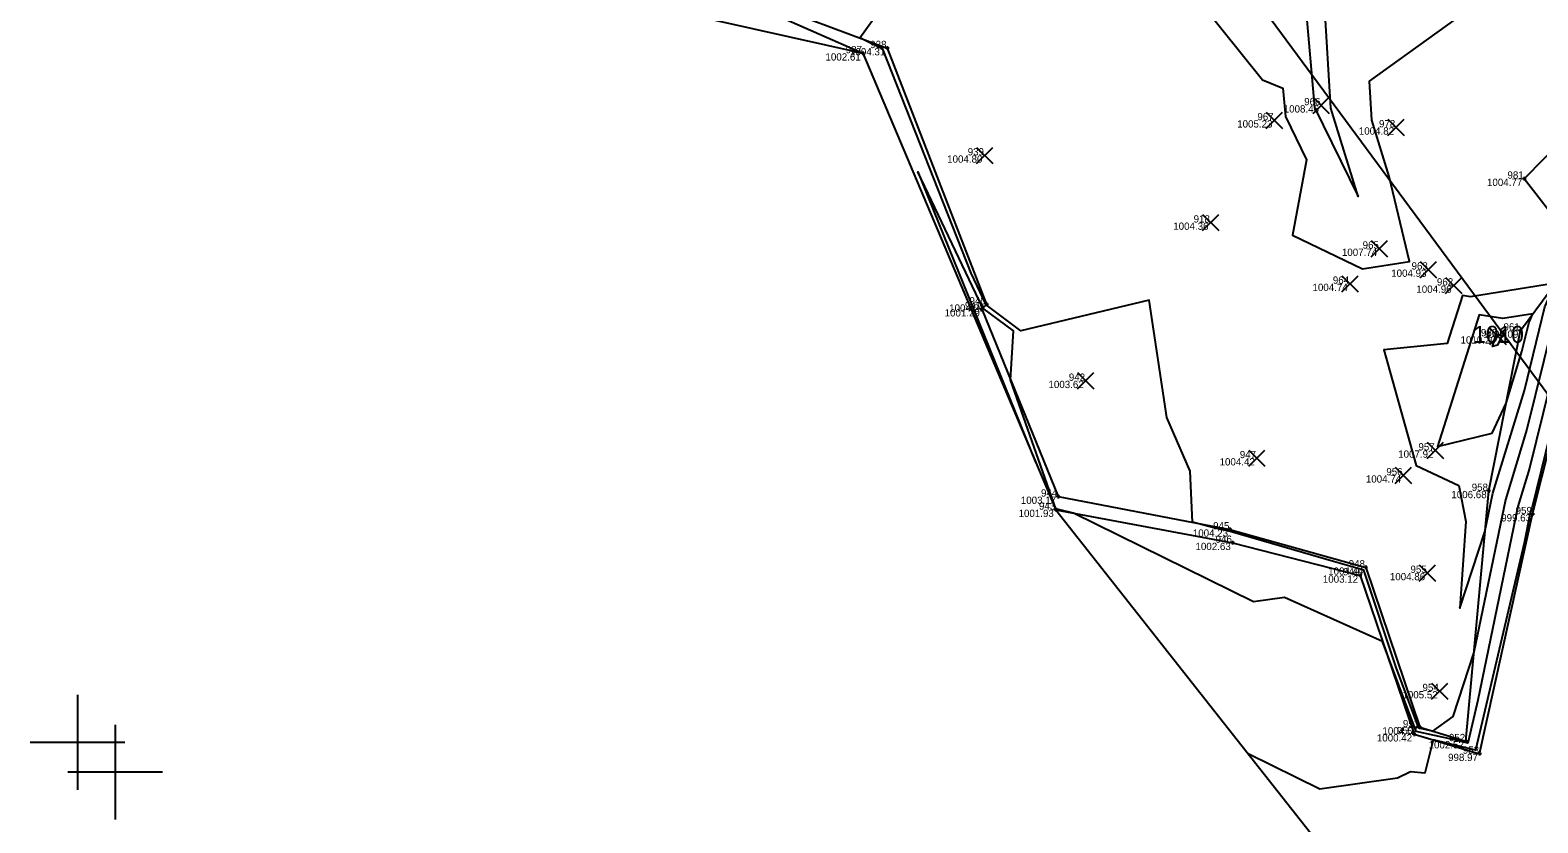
# Model space of a CAD drawing. Extents: x 2354693 to 2355622, y 637071 to 710080.
# Drawn here: x 2355009.4 to 2355257.5, y 709192.3 to 709322.8 of the extents above; entities that cross this region are included whole.
import ezdxf

# ---------------------------------------------------------------- set-up
doc = ezdxf.new("R2010")
doc.units = 0
for name, color, linetype in [('Default', 7, 'Continuous'), ('DT_X_Contour_Major', 7, 'Continuous'), ('DT_X_Contour_Minor', 7, 'Continuous'), ('HY_X_Water_Edge', 7, 'Continuous'), ('SV_X_Random_Point', 7, 'Continuous'), ('SV_X_Shot_Marker', 7, 'Continuous'), ('SV_X_Text_Elevation', 7, 'Continuous'), ('SV_X_Text_Name', 7, 'Continuous'), ('SV_X_Toe_of_Slope', 7, 'Continuous'), ('SV_X_Top_of_Bank', 7, 'Continuous'), ('VG_X_Tree_Line_Rt', 7, 'Continuous')]:
    doc.layers.add(name, color=color, linetype=linetype)

msp = doc.modelspace()

# ---------------------------------------------------------------- linework, layer by layer
at = {"layer": 'Default'}
for p, q in [((2355017.22, 709213.35), (2355017.22, 709197.75)), ((2355023.41, 709208.46), (2355023.41, 709192.86)), ((2355025.02, 709205.55), (2355009.42, 709205.55)), ((2355031.21, 709200.66), (2355015.61, 709200.66))]:
    msp.add_line(p, q, dxfattribs=at)
msp.add_lwpolyline([(2355192.85, 709575.71), (2355160.05, 709542.81), (2355116.76, 709509.42), (2355081.06, 709480.43), (2355058.46, 709461.11), (2355065.45, 709426.86), (2355078.86, 709361.48), (2355116.19, 709325.77), (2355146.4, 709319.01), (2355178.16, 709243.86), (2355227.43, 709181.3), (2355213.36, 709127.54), (2355205.69, 709069.16), (2355203.89, 709062.28), (2355168.12, 708973.83)], dxfattribs=at)
msp.add_lwpolyline([(2355192.85, 709575.71), (2355160.05, 709542.81), (2355116.76, 709509.42), (2355081.06, 709480.43), (2355058.46, 709461.11), (2355065.45, 709426.86), (2355078.86, 709361.48), (2355116.19, 709325.77), (2355146.4, 709319.01), (2355178.16, 709243.86), (2355227.43, 709181.3), (2355213.36, 709127.54), (2355205.69, 709069.16), (2355203.89, 709062.28), (2355168.12, 708973.83)], dxfattribs=at)
at = {"layer": 'DT_X_Contour_Major'}
for points in [[(2355250.64, 709272.73), (2355251.6, 709272.58), (2355250.84, 709270.94), (2355250.01, 709270.74), (2355250.64, 709272.73)], [(2355250.64, 709272.73), (2355251.6, 709272.58), (2355250.84, 709270.94), (2355250.01, 709270.74), (2355250.64, 709272.73)], [(2355259.45, 709256.12), (2355256.53, 709244.3), (2355256.24, 709243.32), (2355255.21, 709238.35), (2355247.24, 709204.27), (2355240.26, 709205.95), (2355238.9, 709200.49), (2355236.53, 709200.69), (2355234.37, 709199.64), (2355221.59, 709197.85), (2355209.81, 709203.68)], [(2355259.45, 709256.12), (2355256.53, 709244.3), (2355256.24, 709243.32), (2355255.21, 709238.35), (2355247.24, 709204.27), (2355240.26, 709205.95), (2355238.9, 709200.49), (2355236.53, 709200.69), (2355234.37, 709199.64), (2355221.59, 709197.85), (2355209.81, 709203.68)]]:
    msp.add_lwpolyline(points, dxfattribs=at)
at = {"layer": 'DT_X_Contour_Minor'}
for points in [[(2355223.4, 709309.98), (2355222.4, 709327.22), (2355227.34, 709330.79), (2355220.07, 709333.56), (2355207.66, 709335.32), (2355213.86, 709359.23), (2355219.29, 709363.85), (2355215.74, 709367.58), (2355211.47, 709363.79), (2355205.57, 709361.18), (2355209.61, 709356.62), (2355205.47, 709333.93), (2355207.14, 709331.84), (2355219.24, 709326.97), (2355220.73, 709310.09), (2355227.94, 709295.41), (2355223.4, 709309.98)], [(2355223.4, 709309.98), (2355222.4, 709327.22), (2355227.34, 709330.79), (2355220.07, 709333.56), (2355207.66, 709335.32), (2355213.86, 709359.23), (2355219.29, 709363.85), (2355215.74, 709367.58), (2355211.47, 709363.79), (2355205.57, 709361.18), (2355209.61, 709356.62), (2355205.47, 709333.93), (2355207.14, 709331.84), (2355219.24, 709326.97), (2355220.73, 709310.09), (2355227.94, 709295.41), (2355223.4, 709309.98)], [(2355261.28, 709279.75), (2355255.69, 709257.09), (2355252.15, 709245.49), (2355246.97, 709220.39), (2355243.51, 709209.81), (2355240.17, 709207.4), (2355237.92, 709207.88), (2355234.18, 709217.9), (2355228.85, 709233.91), (2355223.84, 709235.33), (2355206.89, 709240.29), (2355203.95, 709240.93), (2355200.67, 709241.78), (2355200.28, 709250.22), (2355196.42, 709259.05), (2355193.56, 709278.35), (2355172.41, 709273.32), (2355166.73, 709277.6), (2355164.24, 709282.82), (2355149.71, 709319.71), (2355145.94, 709321.55), (2355154.28, 709333.16)], [(2355261.28, 709279.75), (2355255.69, 709257.09), (2355252.15, 709245.49), (2355246.97, 709220.39), (2355243.51, 709209.81), (2355240.17, 709207.4), (2355237.92, 709207.88), (2355234.18, 709217.9), (2355228.85, 709233.91), (2355223.84, 709235.33), (2355206.89, 709240.29), (2355203.95, 709240.93), (2355200.67, 709241.78), (2355200.28, 709250.22), (2355196.42, 709259.05), (2355193.56, 709278.35), (2355172.41, 709273.32), (2355166.73, 709277.6), (2355164.24, 709282.82), (2355149.71, 709319.71), (2355145.94, 709321.55), (2355154.28, 709333.16)], [(2355198.39, 709331.9), (2355212.18, 709314.63), (2355215.55, 709313.27), (2355215.97, 709308.57), (2355219.45, 709301.47), (2355217.13, 709289.05), (2355228.61, 709283.49), (2355236.39, 709284.71), (2355233.04, 709298.72), (2355230.15, 709307.99), (2355229.78, 709314.4), (2355252.05, 709330.49)], [(2355198.39, 709331.9), (2355212.18, 709314.63), (2355215.55, 709313.27), (2355215.97, 709308.57), (2355219.45, 709301.47), (2355217.13, 709289.05), (2355228.61, 709283.49), (2355236.39, 709284.71), (2355233.04, 709298.72), (2355230.15, 709307.99), (2355229.78, 709314.4), (2355252.05, 709330.49)], [(2355263.89, 709282.26), (2355256.11, 709250.69), (2355254.19, 709244.4), (2355247.6, 709212.47), (2355245.96, 709205.44), (2355243.51, 709206.03), (2355237.47, 709207.33), (2355231.92, 709222.18), (2355215.82, 709229.38), (2355210.71, 709228.67), (2355181.09, 709243.31), (2355179.04, 709243.76), (2355178.18, 709243.99), (2355170.73, 709265.25), (2355171.19, 709273.3), (2355166.19, 709277.06), (2355155.47, 709299.51), (2355174.86, 709251.68)], [(2355263.89, 709282.26), (2355256.11, 709250.69), (2355254.19, 709244.4), (2355247.6, 709212.47), (2355245.96, 709205.44), (2355243.51, 709206.03), (2355237.47, 709207.33), (2355231.92, 709222.18), (2355215.82, 709229.38), (2355210.71, 709228.67), (2355181.09, 709243.31), (2355179.04, 709243.76), (2355178.18, 709243.99), (2355170.73, 709265.25), (2355171.19, 709273.3), (2355166.19, 709277.06), (2355155.47, 709299.51), (2355174.86, 709251.68)], [(2355258.66, 709277.24), (2355260.4, 709281.18), (2355246.4, 709278.91), (2355245.09, 709279.12), (2355242.59, 709271.24), (2355232.14, 709270.2), (2355237.45, 709251.15), (2355244.48, 709247.85), (2355245.62, 709241.89), (2355244.67, 709227.63), (2355248.78, 709240.19), (2355250.1, 709246.57), (2355255.27, 709263.49), (2355258.66, 709277.24)], [(2355258.66, 709277.24), (2355260.4, 709281.18), (2355246.4, 709278.91), (2355245.09, 709279.12), (2355242.59, 709271.24), (2355232.14, 709270.2), (2355237.45, 709251.15), (2355244.48, 709247.85), (2355245.62, 709241.89), (2355244.67, 709227.63), (2355248.78, 709240.19), (2355250.1, 709246.57), (2355255.27, 709263.49), (2355258.66, 709277.24)], [(2355256.04, 709274.73), (2355256.65, 709276.12), (2355251.72, 709275.32), (2355247.86, 709275.92), (2355240.99, 709254.28), (2355249.97, 709256.47), (2355252.26, 709261.41), (2355254.84, 709269.88), (2355256.04, 709274.73)], [(2355256.04, 709274.73), (2355256.65, 709276.12), (2355251.72, 709275.32), (2355247.86, 709275.92), (2355240.99, 709254.28), (2355249.97, 709256.47), (2355252.26, 709261.41), (2355254.84, 709269.88), (2355256.04, 709274.73)]]:
    msp.add_lwpolyline(points, dxfattribs=at)
at = {"layer": 'HY_X_Water_Edge'}
msp.add_lwpolyline([(2355099.14, 709490.23), (2355112.83, 709450.59), (2355116.9, 709430.14), (2355110.74, 709408.55), (2355107.27, 709364.38), (2355126.09, 709328.02), (2355146.4, 709319.01), (2355178.16, 709243.86), (2355207.27, 709238.41), (2355228.23, 709233.04), (2355237.12, 709206.89), (2355247.9, 709203.67), (2355256.61, 709243.12), (2355267.3, 709285.53), (2355279.14, 709298.91), (2355298.35, 709321.78), (2355310.42, 709328.49), (2355317.24, 709340.56)], dxfattribs=at)
at = {"layer": 'SV_X_Random_Point'}
for p, q in [((2355220.5, 709309.11), (2355223.17, 709311.78)), ((2355220.5, 709311.78), (2355223.17, 709309.11)), ((2355212.8, 709306.64), (2355215.46, 709309.31)), ((2355212.8, 709309.31), (2355215.46, 709306.64)), ((2355232.81, 709305.48), (2355235.48, 709308.15)), ((2355232.81, 709308.15), (2355235.48, 709305.48)), ((2355165.13, 709300.85), (2355167.79, 709303.52)), ((2355165.13, 709303.52), (2355167.79, 709300.85)), ((2355202.32, 709289.8), (2355204.98, 709292.47)), ((2355202.32, 709292.47), (2355204.98, 709289.8)), ((2355230.09, 709285.51), (2355232.76, 709288.18)), ((2355230.09, 709288.18), (2355232.76, 709285.51)), ((2355238.13, 709282.06), (2355240.8, 709284.73)), ((2355238.13, 709284.73), (2355240.8, 709282.06)), ((2355225.25, 709279.72), (2355227.92, 709282.39)), ((2355225.25, 709282.39), (2355227.92, 709279.72)), ((2355242.31, 709279.43), (2355244.98, 709282.1)), ((2355242.31, 709282.1), (2355244.98, 709279.43)), ((2355249.59, 709271.07), (2355252.26, 709273.74)), ((2355249.59, 709273.74), (2355252.26, 709271.07)), ((2355181.75, 709263.75), (2355184.42, 709266.42)), ((2355181.75, 709266.42), (2355184.42, 709263.75)), ((2355239.29, 709252.28), (2355241.96, 709254.95)), ((2355239.29, 709254.95), (2355241.96, 709252.28)), ((2355209.91, 709251), (2355212.57, 709253.67)), ((2355209.91, 709253.67), (2355212.57, 709251)), ((2355234.03, 709248.19), (2355236.7, 709250.86)), ((2355234.03, 709250.86), (2355236.7, 709248.19)), ((2355237.96, 709232.1), (2355240.63, 709234.77)), ((2355237.96, 709234.77), (2355240.63, 709232.1)), ((2355240, 709212.65), (2355242.67, 709215.32)), ((2355240, 709215.32), (2355242.67, 709212.65))]:
    msp.add_line(p, q, dxfattribs=at)
at = {"layer": 'SV_X_Shot_Marker'}
for p, q in [((2355146.7, 709319.01), (2355146.1, 709319.01)), ((2355146.4, 709319.31), (2355146.4, 709318.71)), ((2355150.74, 709319.86), (2355150.14, 709319.86)), ((2355150.44, 709320.16), (2355150.44, 709319.56)), ((2355255.56, 709298.36), (2355254.96, 709298.36)), ((2355255.26, 709298.66), (2355255.26, 709298.06)), ((2355166.3, 709276.87), (2355165.7, 709276.87)), ((2355166, 709277.17), (2355166, 709276.57)), ((2355167.09, 709277.66), (2355166.49, 709277.66)), ((2355166.79, 709277.96), (2355166.79, 709277.36)), ((2355254.91, 709273.36), (2355254.31, 709273.36)), ((2355254.61, 709273.66), (2355254.61, 709273.06)), ((2355249.7, 709246.95), (2355249.1, 709246.95)), ((2355249.4, 709247.25), (2355249.4, 709246.65)), ((2355178.86, 709246.01), (2355178.26, 709246.01)), ((2355178.56, 709246.31), (2355178.56, 709245.71)), ((2355178.46, 709243.86), (2355177.86, 709243.86)), ((2355178.16, 709244.16), (2355178.16, 709243.56)), ((2355256.91, 709243.12), (2355256.31, 709243.12)), ((2355256.61, 709243.42), (2355256.61, 709242.82)), ((2355207.13, 709240.61), (2355206.53, 709240.61)), ((2355206.83, 709240.91), (2355206.83, 709240.31)), ((2355207.57, 709238.41), (2355206.97, 709238.41)), ((2355207.27, 709238.71), (2355207.27, 709238.11)), ((2355229.46, 709234.35), (2355228.86, 709234.35)), ((2355229.16, 709234.65), (2355229.16, 709234.05)), ((2355228.53, 709233.04), (2355227.93, 709233.04)), ((2355228.23, 709233.34), (2355228.23, 709232.74)), ((2355237.12, 709207.19), (2355237.12, 709206.59)), ((2355238.35, 709208.04), (2355237.75, 709208.04)), ((2355238.05, 709208.34), (2355238.05, 709207.74)), ((2355237.42, 709206.89), (2355236.82, 709206.89)), ((2355245.92, 709205.75), (2355245.32, 709205.75)), ((2355245.62, 709206.05), (2355245.62, 709205.45)), ((2355248.2, 709203.67), (2355247.6, 709203.67)), ((2355247.9, 709203.97), (2355247.9, 709203.37))]:
    msp.add_line(p, q, dxfattribs=at)
at = {"layer": 'SV_X_Toe_of_Slope'}
msp.add_lwpolyline([(2355099.14, 709490.23), (2355112.83, 709450.59), (2355116.9, 709430.14), (2355110.74, 709408.55), (2355107.27, 709364.38), (2355126.09, 709328.02), (2355146.4, 709319.01), (2355178.16, 709243.86), (2355207.27, 709238.41), (2355228.23, 709233.04), (2355237.12, 709206.89), (2355247.9, 709203.67), (2355256.61, 709243.12), (2355267.3, 709285.53), (2355279.14, 709298.91), (2355298.35, 709321.78), (2355310.42, 709328.49), (2355317.24, 709340.56)], dxfattribs=at)
at = {"layer": 'SV_X_Top_of_Bank'}
msp.add_lwpolyline([(2355100.08, 709490.73), (2355115.52, 709450.05), (2355117.98, 709430.72), (2355113.57, 709407.6), (2355111.71, 709364.49), (2355128.66, 709328.03), (2355150.44, 709319.86), (2355166.79, 709277.66), (2355166, 709276.87), (2355178.56, 709246.01), (2355206.83, 709240.61), (2355229.16, 709234.35), (2355238.05, 709208.04), (2355245.62, 709205.75), (2355249.4, 709246.95), (2355254.61, 709273.36), (2355264.37, 709286.54), (2355255.26, 709298.36), (2355265.16, 709308.45), (2355274.57, 709302.63), (2355292.81, 709328.24), (2355310.42, 709346), (2355315.95, 709345.13)], dxfattribs=at)
at = {"layer": 'VG_X_Tree_Line_Rt'}
msp.add_lwpolyline([(2355286.87, 709031.33), (2355312.43, 709075.83), (2355322.75, 709120.09), (2355304.91, 709171.78), (2355297.85, 709210.36), (2355206.48, 709334.22), (2355207.86, 709373.6), (2355249.36, 709399.77), (2355239.7, 709433.16), (2355219.43, 709459.42), (2355185.29, 709497.16), (2355152.29, 709534.91)], dxfattribs=at)

# ---------------------------------------------------------------- texts
at = {"layer": 'DT_X_Contour_Major'}
msp.add_text('1010', height=2.8, dxfattribs=at).set_placement((2355246.86, 709271.33))
msp.add_text('1010', height=2.8, dxfattribs=at).set_placement((2355246.86, 709271.33))
at = {"layer": 'SV_X_Text_Elevation'}
for s, p in [('1002.61', (2355140.28, 709317.81)), ('1004.31', (2355144.32, 709318.66)), ('1008.46', (2355215.68, 709309.25)), ('1005.23', (2355208.02, 709306.78)), ('1004.82', (2355228.03, 709305.61)), ('1004.80', (2355160.3, 709300.99)), ('1004.77', (2355249.12, 709297.16)), ('1004.36', (2355197.5, 709289.94)), ('1007.74', (2355225.25, 709285.64)), ('1004.93', (2355233.36, 709282.2)), ('1004.74', (2355220.41, 709279.86)), ('1004.96', (2355237.5, 709279.57)), ('1001.29', (2355159.88, 709275.67)), ('1004.20', (2355160.63, 709276.46)), ('1010.20', (2355244.77, 709271.21)), ('1009.09', (2355248.48, 709272.16)), ('1003.62', (2355176.97, 709263.88)), ('1004.42', (2355205.12, 709251.14)), ('1007.92', (2355234.51, 709252.41)), ('1004.74', (2355229.19, 709248.32)), ('1006.68', (2355243.26, 709245.75)), ('1003.17', (2355172.42, 709244.81)), ('1001.93', (2355172.05, 709242.66)), ('999.63', (2355251.46, 709241.92)), ('1004.23', (2355200.72, 709239.41)), ('1002.63', (2355201.16, 709237.21)), ('1004.44', (2355222.99, 709233.15)), ('1003.12', (2355222.11, 709231.84)), ('1004.86', (2355233.14, 709232.24)), ('1005.52', (2355235.21, 709212.79)), ('1004.57', (2355231.92, 709206.84)), ('1000.42', (2355231, 709205.69)), ('1002.52', (2355239.51, 709204.55)), ('998.97', (2355242.72, 709202.47))]:
    msp.add_text(s, height=1.2, dxfattribs=at).set_placement(p)
at = {"layer": 'SV_X_Text_Name'}
for s, p in [('937', (2355143.61, 709319.01)), ('938', (2355147.64, 709319.86)), ('966', (2355219.04, 709310.45)), ('967', (2355211.34, 709307.98)), ('978', (2355231.35, 709306.81)), ('939', (2355163.68, 709302.19)), ('981', (2355252.49, 709298.36)), ('918', (2355200.85, 709291.14)), ('965', (2355228.66, 709286.84)), ('963', (2355236.71, 709283.4)), ('964', (2355223.76, 709281.06)), ('962', (2355240.88, 709280.77)), ('941', (2355163.23, 709276.87)), ('940', (2355163.98, 709277.66)), ('961', (2355251.84, 709273.36)), ('960', (2355248.12, 709272.41)), ('942', (2355180.32, 709265.08)), ('957', (2355237.84, 709253.61)), ('947', (2355208.45, 709252.34)), ('956', (2355232.56, 709249.52)), ('944', (2355175.74, 709246.01)), ('958', (2355246.61, 709246.95)), ('943', (2355175.4, 709243.86)), ('959', (2355253.83, 709243.12)), ('945', (2355204.06, 709240.61)), ('946', (2355204.47, 709238.41)), ('948', (2355226.37, 709234.35)), ('955', (2355236.53, 709233.44)), ('949', (2355225.45, 709233.04)), ('954', (2355238.51, 709213.99)), ('950', (2355234.31, 709206.89)), ('951', (2355235.28, 709208.04)), ('952', (2355242.86, 709205.75)), ('953', (2355245.14, 709203.67))]:
    msp.add_text(s, height=1.2, dxfattribs=at).set_placement(p)

doc.saveas('drawing.dxf')
